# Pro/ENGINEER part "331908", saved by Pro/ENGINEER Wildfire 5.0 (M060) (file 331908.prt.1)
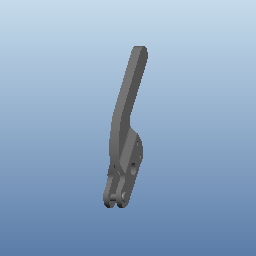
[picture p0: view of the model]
Units: PSOLunit; MM, KILOGRAM, SECS

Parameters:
  NN = "331908"
  NT = "Stainless Steel - Latch Clamps - 331-RSS Series - Handle"
  NB = "331908"
  NBSYN = "$PN."
  LINA = "331908"
  S = "331-rss"
  PN = "331908"
  ARTICLENO = "331908"
  BOMINFO = "331908"
  CREATOR = "CADENAS GmbH"

Other parameters: A1, A2, A3, A4, A5, A6, A7, A8, A9, B1, B2, B3, B4, B5, B6, B7, B8, B9, C5, C6, C7, C8, C9, SURF_AREA, MASS

Other named items: COORD, DEF-PLANE-AXIS, DEF-PLANE-AXIS-INV, CS0, CS1, HANDLE_TO_BASE_CSYS, HANDLE_TO_GRIP_CSYS, HANDLE_TO_LEVER_CSYS, HANDLE_TO_PIN_CSYS, CONN, MASS, RIGHT, TOP, FRONT, HANDLE_TO_BASE_XPLN, HANDLE_TO_BASE_YPLN, HANDLE_TO_BASE_ZPLN, HANDLE_TO_GRIP_XPLN, HANDLE_TO_GRIP_YPLN, HANDLE_TO_GRIP_ZPLN, HANDLE_TO_LEVER_XPLN, HANDLE_TO_LEVER_YPLN, HANDLE_TO_LEVER_ZPLN, HANDLE_TO_PIN_XPLN, HANDLE_TO_PIN_YPLN, HANDLE_TO_PIN_ZPLN, HANDLE_TO_BASE_ZAXS, HANDLE_TO_GRIP_ZAXS, HANDLE_TO_LEVER_ZAXS, HANDLE_TO_PIN_ZAXS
